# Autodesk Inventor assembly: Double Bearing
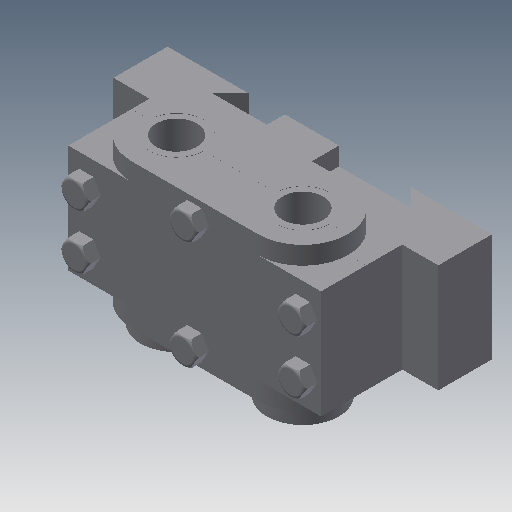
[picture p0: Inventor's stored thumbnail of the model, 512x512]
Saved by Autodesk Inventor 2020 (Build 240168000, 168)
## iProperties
Created: 2002-02
Part Number: Double Bearing
Document SubType Name: Assembly
Designer: ***
Control State: 0
Master: False
Checked Out: False
Shininess: 64.0
Length Units: 11269
Angle Units: 11279
Time Units: 11290
Mass Units: 11283
Length Display Precision: 3
Angle Display Precision: 2
Density: 0.0
Volumn: 0.0
Area: 0.0
PropertySet Name: Model Information
Author: ***
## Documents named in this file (5)
- D:\Autodesk Inventor_2020\Resources\Resources\Inventor_2020_Part\Inventor_2020_Part\c12_Inv_2019_prt\fig-12-10 and 12-18\Double Bearing.iam
- D:\Autodesk Inventor_2020\Resources\Resources\Inventor_2020_Part\Inventor_2020_Part\c12_Inv_2019_prt\fig-12-10 and 12-18\Base.ipt
- D:\Autodesk Inventor_2020\Resources\Resources\Inventor_2020_Part\Inventor_2020_Part\c12_Inv_2019_prt\fig-12-10 and 12-18\Cap.ipt
- D:\Autodesk Inventor_2020\Resources\Resources\Inventor_2020_Part\Inventor_2020_Part\c12_Inv_2019_prt\fig-12-10 and 12-18\Bushing.ipt
- D:\Autodesk Inventor_2020\Resources\Resources\Inventor_2020_Part\Inventor_2020_Part\c12_Inv_2019_prt\fig-12-10 and 12-18\Bolt.ipt
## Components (10 placed, 4 different names)
1. Base:1 — Insert:1, Insert:2
2. Cap:1 — Insert:1, Insert:2, Insert:3, Insert:4, Insert:5, Insert:6
3. Bushing:1 — Insert:3
4. Bushing:2 — Insert:4
5. Bolt:1 — Insert:5
6. Bolt:6
7. Bolt:7
8. Bolt:8
9. Bolt:5 — Insert:6
10. Bolt:9
## Component patterns: Component Pattern 1 (4 elements), Component Pattern 2 (2 elements)
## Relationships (6: Insert 6)
- Insert:1: Base:1 ↔ Cap:1
- Insert:2: Base:1 ↔ Cap:1
- Insert:3: Cap:1 ↔ Bushing:1
- Insert:4: Cap:1 ↔ Bushing:2
- Insert:5: Cap:1 ↔ Bolt:1
- Insert:6: Cap:1 ↔ Bolt:5
